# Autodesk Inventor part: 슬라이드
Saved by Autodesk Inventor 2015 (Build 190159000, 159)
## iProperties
Created: 2025-08
Part Number: 슬라이드
Material: 일반
Document SubType Name: Modeling
Designer: user
Density: 1 g/cm^3
Appearance: 기본값
Author: user
Author: jhkim
Creation Date: 2025-08-05
Sending System: Autodesk Inventor 2026
Preprocessor: ST-DEVELOPER v20.1
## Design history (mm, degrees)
node "슬라이드1"
node "솔리드1"
node "기준1"
